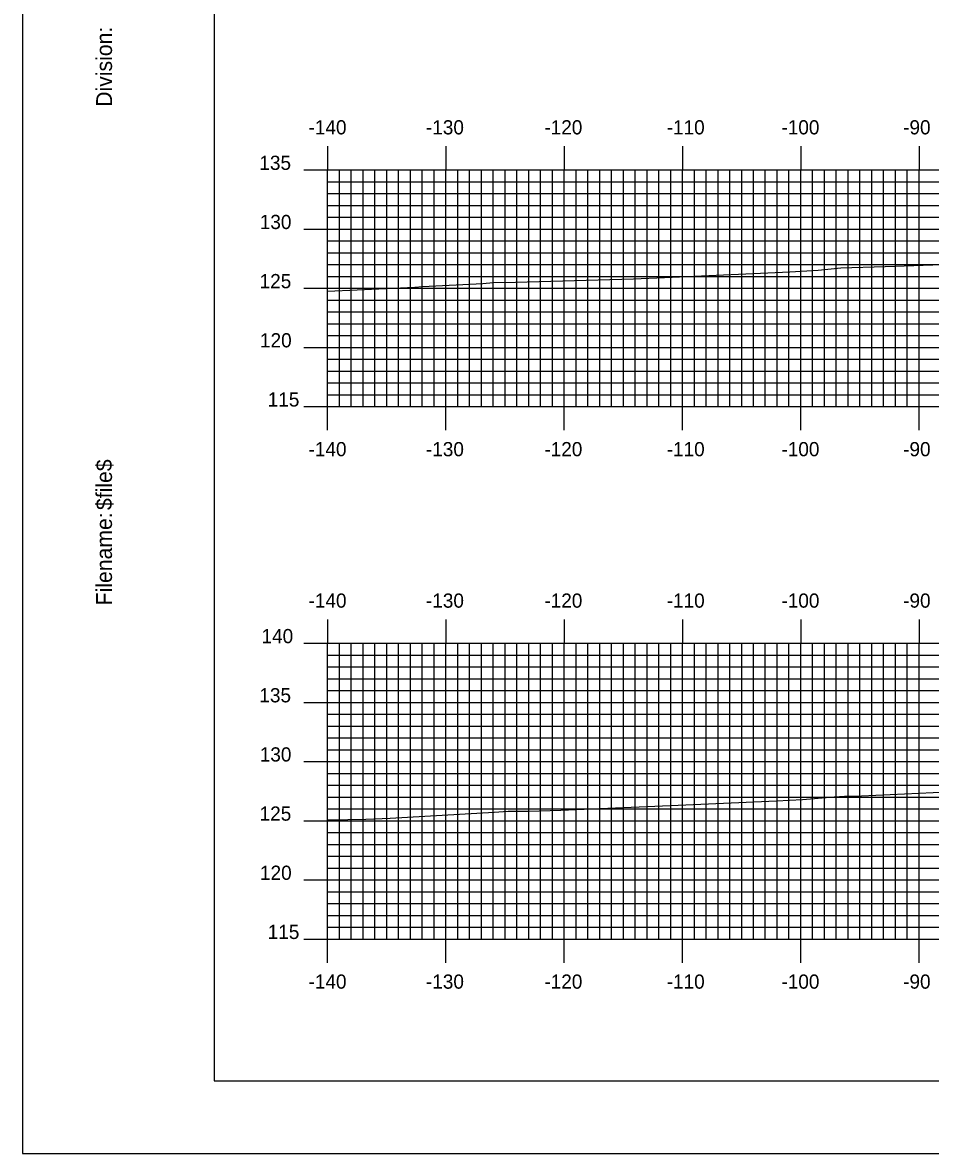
# Model space of a CAD drawing. Extents: x 842175 to 842518, y 363538 to 363758.
# Drawn here: x 842175.1 to 842251.8, y 363537.6 to 363633.2 of the extents above; entities that cross this region are included whole.
import ezdxf

# ---------------------------------------------------------------- set-up
doc = ezdxf.new("R2010")
doc.units = 0
for name, color, linetype in [('BORDER', 7, 'Continuous'), ('H_V ANNOTATION', 7, 'Continuous'), ('M_Roadway_Centerline', 7, 'Continuous'), ('MAJOR', 7, 'Continuous'), ('MINOR', 7, 'Continuous'), ('PLOT BOUNDARY', 7, 'Continuous'), ('S_Roadway_Centerline', 7, 'Continuous')]:
    doc.layers.add(name, color=color, linetype=linetype)

msp = doc.modelspace()

# ---------------------------------------------------------------- linework, layer by layer
at = {"layer": 'BORDER'}
msp.add_lwpolyline([(842191.285, 363543.721), (842511.285, 363543.721), (842511.285, 363753.721), (842191.285, 363753.721)], close=True, dxfattribs=at)
at = {"layer": 'MAJOR'}
for p, q in [((842200.885, 363622.725), (842200.885, 363620.721)), ((842210.885, 363622.725), (842210.885, 363620.721)), ((842220.885, 363622.725), (842220.885, 363620.721)), ((842230.885, 363622.725), (842230.885, 363620.721)), ((842240.885, 363622.725), (842240.885, 363620.721)), ((842250.885, 363622.725), (842250.885, 363620.721)), ((842198.881, 363620.721), (842200.885, 363620.721)), ((842200.885, 363620.721), (842480.885, 363620.721)), ((842200.885, 363600.721), (842200.885, 363620.721)), ((842200.885, 363600.721), (842200.885, 363620.721)), ((842200.885, 363620.721), (842480.885, 363620.721)), ((842210.885, 363600.721), (842210.885, 363620.721)), ((842220.885, 363600.721), (842220.885, 363620.721)), ((842230.885, 363600.721), (842230.885, 363620.721)), ((842240.885, 363600.721), (842240.885, 363620.721)), ((842250.885, 363600.721), (842250.885, 363620.721)), ((842198.881, 363615.721), (842200.885, 363615.721)), ((842200.885, 363615.721), (842480.885, 363615.721)), ((842198.881, 363610.721), (842200.885, 363610.721)), ((842200.885, 363610.721), (842480.885, 363610.721)), ((842198.881, 363605.721), (842200.885, 363605.721)), ((842200.885, 363605.721), (842480.885, 363605.721)), ((842198.881, 363600.721), (842200.885, 363600.721)), ((842200.885, 363600.721), (842480.885, 363600.721)), ((842200.885, 363600.721), (842480.885, 363600.721)), ((842200.885, 363598.717), (842200.885, 363600.721)), ((842210.885, 363598.717), (842210.885, 363600.721)), ((842220.885, 363598.717), (842220.885, 363600.721)), ((842230.885, 363598.717), (842230.885, 363600.721)), ((842240.885, 363598.717), (842240.885, 363600.721)), ((842250.885, 363598.717), (842250.885, 363600.721)), ((842200.885, 363582.725), (842200.885, 363580.721)), ((842210.885, 363582.725), (842210.885, 363580.721)), ((842220.885, 363582.725), (842220.885, 363580.721)), ((842230.885, 363582.725), (842230.885, 363580.721)), ((842240.885, 363582.725), (842240.885, 363580.721)), ((842250.885, 363582.725), (842250.885, 363580.721)), ((842198.881, 363580.721), (842200.885, 363580.721)), ((842200.885, 363580.721), (842480.885, 363580.721)), ((842200.885, 363555.721), (842200.885, 363580.721)), ((842200.885, 363555.721), (842200.885, 363580.721)), ((842200.885, 363580.721), (842480.885, 363580.721)), ((842210.885, 363555.721), (842210.885, 363580.721)), ((842220.885, 363555.721), (842220.885, 363580.721)), ((842230.885, 363555.721), (842230.885, 363580.721)), ((842240.885, 363555.721), (842240.885, 363580.721)), ((842250.885, 363555.721), (842250.885, 363580.721)), ((842198.881, 363575.721), (842200.885, 363575.721)), ((842200.885, 363575.721), (842480.885, 363575.721)), ((842198.881, 363570.721), (842200.885, 363570.721)), ((842200.885, 363570.721), (842480.885, 363570.721)), ((842198.881, 363565.721), (842200.885, 363565.721)), ((842200.885, 363565.721), (842480.885, 363565.721)), ((842198.881, 363560.721), (842200.885, 363560.721)), ((842200.885, 363560.721), (842480.885, 363560.721)), ((842198.881, 363555.721), (842200.885, 363555.721)), ((842200.885, 363555.721), (842480.885, 363555.721)), ((842200.885, 363555.721), (842480.885, 363555.721)), ((842200.885, 363553.717), (842200.885, 363555.721)), ((842210.885, 363553.717), (842210.885, 363555.721)), ((842220.885, 363553.717), (842220.885, 363555.721)), ((842230.885, 363553.717), (842230.885, 363555.721)), ((842240.885, 363553.717), (842240.885, 363555.721)), ((842250.885, 363553.717), (842250.885, 363555.721))]:
    msp.add_line(p, q, dxfattribs=at)
at = {"layer": 'MINOR'}
for p, q in [((842201.885, 363600.721), (842201.885, 363620.721)), ((842202.885, 363600.721), (842202.885, 363620.721)), ((842203.885, 363600.721), (842203.885, 363620.721)), ((842204.885, 363600.721), (842204.885, 363620.721)), ((842205.885, 363600.721), (842205.885, 363620.721)), ((842206.885, 363600.721), (842206.885, 363620.721)), ((842207.885, 363600.721), (842207.885, 363620.721)), ((842208.885, 363600.721), (842208.885, 363620.721)), ((842209.885, 363600.721), (842209.885, 363620.721)), ((842211.885, 363600.721), (842211.885, 363620.721)), ((842212.885, 363600.721), (842212.885, 363620.721)), ((842213.885, 363600.721), (842213.885, 363620.721)), ((842214.885, 363600.721), (842214.885, 363620.721)), ((842215.885, 363600.721), (842215.885, 363620.721)), ((842216.885, 363600.721), (842216.885, 363620.721)), ((842217.885, 363600.721), (842217.885, 363620.721)), ((842218.885, 363600.721), (842218.885, 363620.721)), ((842219.885, 363600.721), (842219.885, 363620.721)), ((842221.885, 363600.721), (842221.885, 363620.721)), ((842222.885, 363600.721), (842222.885, 363620.721)), ((842223.885, 363600.721), (842223.885, 363620.721)), ((842224.885, 363600.721), (842224.885, 363620.721)), ((842225.885, 363600.721), (842225.885, 363620.721)), ((842226.885, 363600.721), (842226.885, 363620.721)), ((842227.885, 363600.721), (842227.885, 363620.721)), ((842228.885, 363600.721), (842228.885, 363620.721)), ((842229.885, 363600.721), (842229.885, 363620.721)), ((842231.885, 363600.721), (842231.885, 363620.721)), ((842232.885, 363600.721), (842232.885, 363620.721)), ((842233.885, 363600.721), (842233.885, 363620.721)), ((842234.885, 363600.721), (842234.885, 363620.721)), ((842235.885, 363600.721), (842235.885, 363620.721)), ((842236.885, 363600.721), (842236.885, 363620.721)), ((842237.885, 363600.721), (842237.885, 363620.721)), ((842238.885, 363600.721), (842238.885, 363620.721)), ((842239.885, 363600.721), (842239.885, 363620.721)), ((842241.885, 363600.721), (842241.885, 363620.721)), ((842242.885, 363600.721), (842242.885, 363620.721)), ((842243.885, 363600.721), (842243.885, 363620.721)), ((842244.885, 363600.721), (842244.885, 363620.721)), ((842245.885, 363600.721), (842245.885, 363620.721)), ((842246.885, 363600.721), (842246.885, 363620.721)), ((842247.885, 363600.721), (842247.885, 363620.721)), ((842248.885, 363600.721), (842248.885, 363620.721)), ((842249.885, 363600.721), (842249.885, 363620.721)), ((842200.885, 363619.721), (842480.885, 363619.721)), ((842200.885, 363619.721), (842202.889, 363619.721)), ((842200.885, 363618.721), (842480.885, 363618.721)), ((842200.885, 363618.721), (842202.889, 363618.721)), ((842200.885, 363617.721), (842480.885, 363617.721)), ((842200.885, 363617.721), (842202.889, 363617.721)), ((842200.885, 363616.721), (842480.885, 363616.721)), ((842200.885, 363616.721), (842202.889, 363616.721)), ((842200.885, 363614.721), (842480.885, 363614.721)), ((842200.885, 363614.721), (842202.889, 363614.721)), ((842200.885, 363613.721), (842480.885, 363613.721)), ((842200.885, 363613.721), (842202.889, 363613.721)), ((842200.885, 363612.721), (842480.885, 363612.721)), ((842200.885, 363612.721), (842202.889, 363612.721)), ((842200.885, 363611.721), (842480.885, 363611.721)), ((842200.885, 363611.721), (842202.889, 363611.721)), ((842200.885, 363609.721), (842480.885, 363609.721)), ((842200.885, 363609.721), (842202.889, 363609.721)), ((842200.885, 363608.721), (842480.885, 363608.721)), ((842200.885, 363608.721), (842202.889, 363608.721)), ((842200.885, 363607.721), (842480.885, 363607.721)), ((842200.885, 363607.721), (842202.889, 363607.721)), ((842200.885, 363606.721), (842480.885, 363606.721)), ((842200.885, 363606.721), (842202.889, 363606.721)), ((842200.885, 363604.721), (842480.885, 363604.721)), ((842200.885, 363604.721), (842202.889, 363604.721)), ((842200.885, 363603.721), (842480.885, 363603.721)), ((842200.885, 363603.721), (842202.889, 363603.721)), ((842200.885, 363602.721), (842480.885, 363602.721)), ((842200.885, 363602.721), (842202.889, 363602.721)), ((842200.885, 363601.721), (842480.885, 363601.721)), ((842200.885, 363601.721), (842202.889, 363601.721)), ((842201.885, 363555.721), (842201.885, 363580.721)), ((842202.885, 363555.721), (842202.885, 363580.721)), ((842203.885, 363555.721), (842203.885, 363580.721)), ((842204.885, 363555.721), (842204.885, 363580.721)), ((842205.885, 363555.721), (842205.885, 363580.721)), ((842206.885, 363555.721), (842206.885, 363580.721)), ((842207.885, 363555.721), (842207.885, 363580.721)), ((842208.885, 363555.721), (842208.885, 363580.721)), ((842209.885, 363555.721), (842209.885, 363580.721)), ((842211.885, 363555.721), (842211.885, 363580.721)), ((842212.885, 363555.721), (842212.885, 363580.721)), ((842213.885, 363555.721), (842213.885, 363580.721)), ((842214.885, 363555.721), (842214.885, 363580.721)), ((842215.885, 363555.721), (842215.885, 363580.721)), ((842216.885, 363555.721), (842216.885, 363580.721)), ((842217.885, 363555.721), (842217.885, 363580.721)), ((842218.885, 363555.721), (842218.885, 363580.721)), ((842219.885, 363555.721), (842219.885, 363580.721)), ((842221.885, 363555.721), (842221.885, 363580.721)), ((842222.885, 363555.721), (842222.885, 363580.721)), ((842223.885, 363555.721), (842223.885, 363580.721)), ((842224.885, 363555.721), (842224.885, 363580.721)), ((842225.885, 363555.721), (842225.885, 363580.721)), ((842226.885, 363555.721), (842226.885, 363580.721)), ((842227.885, 363555.721), (842227.885, 363580.721)), ((842228.885, 363555.721), (842228.885, 363580.721)), ((842229.885, 363555.721), (842229.885, 363580.721)), ((842231.885, 363555.721), (842231.885, 363580.721)), ((842232.885, 363555.721), (842232.885, 363580.721)), ((842233.885, 363555.721), (842233.885, 363580.721)), ((842234.885, 363555.721), (842234.885, 363580.721)), ((842235.885, 363555.721), (842235.885, 363580.721)), ((842236.885, 363555.721), (842236.885, 363580.721)), ((842237.885, 363555.721), (842237.885, 363580.721)), ((842238.885, 363555.721), (842238.885, 363580.721)), ((842239.885, 363555.721), (842239.885, 363580.721)), ((842241.885, 363555.721), (842241.885, 363580.721)), ((842242.885, 363555.721), (842242.885, 363580.721)), ((842243.885, 363555.721), (842243.885, 363580.721)), ((842244.885, 363555.721), (842244.885, 363580.721)), ((842245.885, 363555.721), (842245.885, 363580.721)), ((842246.885, 363555.721), (842246.885, 363580.721)), ((842247.885, 363555.721), (842247.885, 363580.721)), ((842248.885, 363555.721), (842248.885, 363580.721)), ((842249.885, 363555.721), (842249.885, 363580.721)), ((842200.885, 363579.721), (842480.885, 363579.721)), ((842200.885, 363579.721), (842202.889, 363579.721)), ((842200.885, 363578.721), (842480.885, 363578.721)), ((842200.885, 363578.721), (842202.889, 363578.721)), ((842200.885, 363577.721), (842480.885, 363577.721)), ((842200.885, 363577.721), (842202.889, 363577.721)), ((842200.885, 363576.721), (842480.885, 363576.721)), ((842200.885, 363576.721), (842202.889, 363576.721)), ((842200.885, 363574.721), (842480.885, 363574.721)), ((842200.885, 363574.721), (842202.889, 363574.721)), ((842200.885, 363573.721), (842480.885, 363573.721)), ((842200.885, 363573.721), (842202.889, 363573.721)), ((842200.885, 363572.721), (842480.885, 363572.721)), ((842200.885, 363572.721), (842202.889, 363572.721)), ((842200.885, 363571.721), (842480.885, 363571.721)), ((842200.885, 363571.721), (842202.889, 363571.721)), ((842200.885, 363569.721), (842480.885, 363569.721)), ((842200.885, 363569.721), (842202.889, 363569.721)), ((842200.885, 363568.721), (842480.885, 363568.721)), ((842200.885, 363568.721), (842202.889, 363568.721)), ((842200.885, 363567.721), (842480.885, 363567.721)), ((842200.885, 363567.721), (842202.889, 363567.721)), ((842200.885, 363566.721), (842480.885, 363566.721)), ((842200.885, 363566.721), (842202.889, 363566.721)), ((842200.885, 363564.721), (842480.885, 363564.721)), ((842200.885, 363564.721), (842202.889, 363564.721)), ((842200.885, 363563.721), (842480.885, 363563.721)), ((842200.885, 363563.721), (842202.889, 363563.721)), ((842200.885, 363562.721), (842480.885, 363562.721)), ((842200.885, 363562.721), (842202.889, 363562.721)), ((842200.885, 363561.721), (842480.885, 363561.721)), ((842200.885, 363561.721), (842202.889, 363561.721)), ((842200.885, 363559.721), (842480.885, 363559.721)), ((842200.885, 363559.721), (842202.889, 363559.721)), ((842200.885, 363558.721), (842480.885, 363558.721)), ((842200.885, 363558.721), (842202.889, 363558.721)), ((842200.885, 363557.721), (842480.885, 363557.721)), ((842200.885, 363557.721), (842202.889, 363557.721)), ((842200.885, 363556.721), (842480.885, 363556.721)), ((842200.885, 363556.721), (842202.889, 363556.721))]:
    msp.add_line(p, q, dxfattribs=at)
at = {"layer": 'PLOT BOUNDARY'}
msp.add_lwpolyline([(842175.098, 363537.603), (842515.098, 363537.603), (842515.098, 363757.603), (842175.098, 363757.603)], close=True, dxfattribs=at)
at = {"layer": 'S_Roadway_Centerline'}
for points in [[(842200.885, 363610.472), (842203.393, 363610.581), (842208.261, 363610.802), (842208.898, 363610.869), (842213.998, 363611.13), (842214.871, 363611.2), (842216.765, 363611.221), (842226.751, 363611.508), (842230.015, 363611.649), (842239.959, 363612.096), (842242.339, 363612.233), (842244.278, 363612.439), (842248.006, 363612.543), (842252.059, 363612.702)], [(842200.885, 363565.785), (842201.071, 363565.806), (842204.124, 363565.837), (842206.167, 363565.931), (842214.964, 363566.447), (842216.137, 363566.535), (842216.314, 363566.531), (842217.861, 363566.529), (842220.594, 363566.602), (842230.505, 363567.019), (842238.836, 363567.397), (842241.039, 363567.51), (842243.693, 363567.725), (842244.574, 363567.803), (842246.018, 363567.829), (842253.285, 363568.157)]]:
    msp.add_lwpolyline(points, dxfattribs=at)

# ---------------------------------------------------------------- texts
at = {"layer": 'BORDER'}
for s, p in [('Division:', (842182.655, 363626.053)), ('$file$', (842182.655, 363591.972)), ('Filename:', (842182.655, 363583.918))]:
    msp.add_text(s, height=1.3392, rotation=90, dxfattribs=at).set_placement(p)
at = {"layer": 'H_V ANNOTATION'}
for s, p in [('-140', (842199.269, 363623.721)), ('-130', (842209.194, 363623.721)), ('-120', (842219.205, 363623.721)), ('-110', (842229.547, 363623.721)), ('-100', (842239.247, 363623.721)), ('-90', (842249.536, 363623.721)), ('135', (842195.113, 363620.721)), ('130', (842195.145, 363615.721)), ('125', (842195.134, 363610.721)), ('120', (842195.166, 363605.721)), ('115', (842195.819, 363600.721)), ('-140', (842199.269, 363596.521)), ('-130', (842209.194, 363596.521)), ('-120', (842219.205, 363596.521)), ('-110', (842229.547, 363596.521)), ('-100', (842239.247, 363596.521)), ('-90', (842249.536, 363596.521)), ('-140', (842199.269, 363583.721)), ('-130', (842209.194, 363583.721)), ('-120', (842219.205, 363583.721)), ('-110', (842229.547, 363583.721)), ('-100', (842239.247, 363583.721)), ('-90', (842249.536, 363583.721)), ('140', (842195.295, 363580.721)), ('135', (842195.113, 363575.721)), ('130', (842195.145, 363570.721)), ('125', (842195.134, 363565.721)), ('120', (842195.166, 363560.721)), ('115', (842195.819, 363555.721)), ('-140', (842199.269, 363551.521)), ('-130', (842209.194, 363551.521)), ('-120', (842219.205, 363551.521)), ('-110', (842229.547, 363551.521)), ('-100', (842239.247, 363551.521)), ('-90', (842249.536, 363551.521))]:
    msp.add_text(s, height=1.2, dxfattribs=at).set_placement(p)
at = {"layer": 'M_Roadway_Centerline'}
for s, p in [('C', (842244.273, 363612.439)), ('L', (842244.278, 363612.431)), ('C', (842214.866, 363611.2)), ('L', (842214.871, 363611.192)), ('C', (842244.569, 363567.803)), ('L', (842244.574, 363567.795)), ('C', (842216.132, 363566.535)), ('L', (842216.137, 363566.527))]:
    msp.add_text(s, height=0.0146, dxfattribs=at).set_placement(p)
at = {"layer": 'MAJOR'}
for p in [(842200.876, 363600.721), (842200.876, 363555.721)]:
    msp.add_text('-', height=0.012, dxfattribs=at).set_placement(p)

doc.saveas('drawing.dxf')
